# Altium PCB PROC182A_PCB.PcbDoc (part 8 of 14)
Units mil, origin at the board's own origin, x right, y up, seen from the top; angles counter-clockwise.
Board outline 3168.31 x 3700.79 mil, 8 copper layers (Top Layer, L2_GND1, L3_SIG1, L4_PWR1, L5_PWR2, L6_SIG2, L7_GND2, Bottom Layer), stack 58.1 mil thick; 580 components, 391 nets, 8314 pads, 4370 vias.
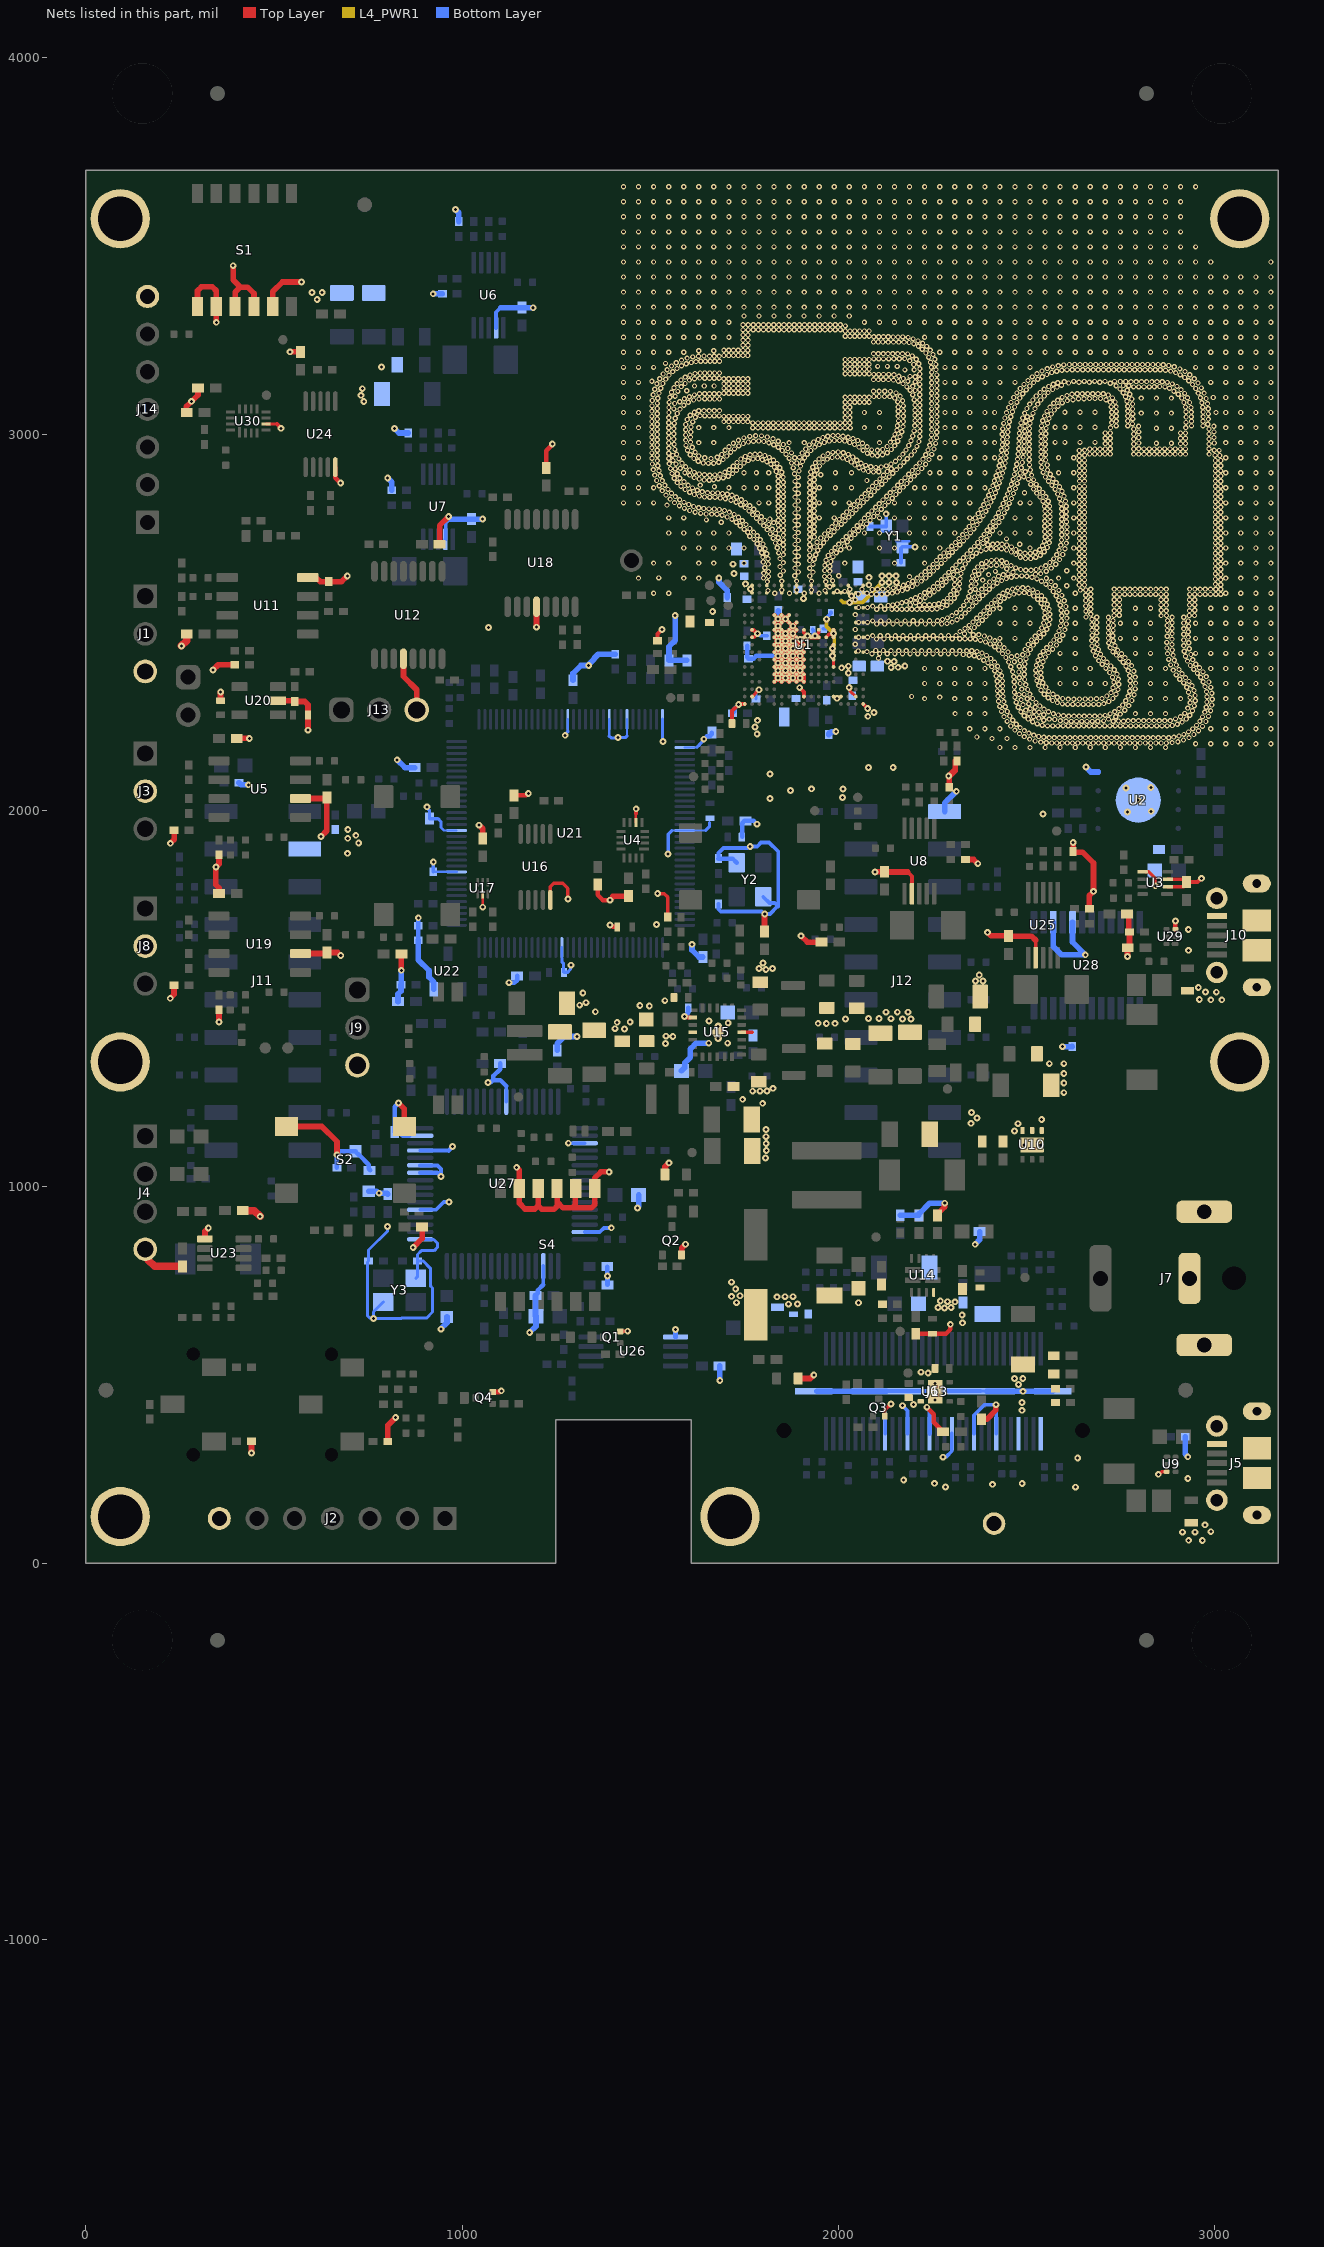
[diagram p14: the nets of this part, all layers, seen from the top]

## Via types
v1: diameter 13.77, hole 7, Top Layer to L2_GND1, tented both sides, 3444 vias
v2: diameter 18, hole 8, Top Layer to Bottom Layer, tented both sides, 911 vias
v3: diameter 13.77, hole 7, Top Layer to L2_GND1, tented top, 9 vias
v4: diameter 19.68, hole 7.87, Top Layer to Bottom Layer, 4 vias
v5: diameter 19.68, hole 7.87, Top Layer to Bottom Layer, tented both sides, 2 vias

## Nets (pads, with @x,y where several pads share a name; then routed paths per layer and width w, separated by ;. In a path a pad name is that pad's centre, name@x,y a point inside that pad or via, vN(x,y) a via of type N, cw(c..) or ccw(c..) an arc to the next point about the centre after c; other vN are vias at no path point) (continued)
GND: C1.1 C2.1 C3.1 C4.1 C5.1 C6.2 C7.1 C8.1 C9.1 C10.1 C11.1 C12.1 C13.2 C14.1 C15.2 C16.1 C17.1 C18.1 C19.1 C20.1 C21.1 C22.1 C24.1 C25.1 C26.1 C27.1 C30.2 C31.2 C32.1 C33.1 C34.2 C35.1 C36.2 C37.1 C38.1 C39.1 C40.2 C41.2 C42.1 C43.2 C44.2 C45.1 C46.1 C47.2 C48.2 C49.2 C50.2 C51.2 C52.1 C53.2 C54.2 C55.2 C56.2 C57.2 C58.2 C59.2 C60.2 C61.2 C62.2 C63.2 C64.2 C65.2 C66.2 C67.1 C68.2 C70.2 C71.2 C72.1 C73.2 C74.2 C75.1 C76.2 C77.1 C78.1 C79.2 C80.2 C81.2 C82.1 C83.2 C84.2 C85.1 C86.1 C87.2 C88.1 C89.2 C90.2 C91.1 C92.2 C93.2 C94.2 C95.1 C96.1 C97.1 C98.1 C99.1 C100.2 C102.1 C103.1 C104.2 C105.2 C106.1 C107.2 C108.2 C109.1 C110.1 C111.1 C112.1 C113.1 C114.2 C115.2 C116.1 C117.1 C118.1 C119.2 C120.2 C121.1 C123.2 C124.2 C125.1 C126.1 C127.2 C128.2 C130.2 C131.1 C132.2 C133.2 C134.1 C135.2 C136.2 C137.2 C138.2 C139.2 C140.2 C141.2 C142.1 C143.2 C144.2 C145.2 C146.1 C147.2 C148.2 C149.1 C150.2 C151.1 C152.2 C153.2 C154.1 C155.1 C156.1 C157.1 C158.2 D6.1 D10.1 J1.3 J2.7 J3.2 J4.4 J5.5 J5.6 J5.7 J5.8 J5.9 J5.10 J5.11 J6.18 J6.24 J6.30 J6.36 J6.42 J6.48 J6.54 J6.60 J6.MP1 J6.MP2 J6.MP3 J6.MP4 J7.2 J7.S1 J7.S2 J8.2 J9.3 J10.5 J10.6 J10.7 J10.8 J10.9 J10.10 J10.11 J11.4 J12.2 J13.3 J14.7 pad.TH1 pad.TH2 pad.TH9 Q1.2 Q2.2 Q3.2 Q4.2 R6.1 R10.2 R11.1 R20.1 R23.1 R33.1 R57.1 R71.1 R72.1 R73.2 R74.1 R75.1 R84.1 R86.1 R92.1 R101.1 R103.1 R113.1 R114.1 R116.1 R117.1 R144.1 R148.1 R150.1 R158.1 R162.1 R191.2 R194.2 R205.1 R208.1 R215.2 R218.1 R234.1 R239.1 R260.1 R265.2 R272.1 R276.2 R289.1 S1.7 S1.8 S1.9 S1.10 S1.11 S2.1 S2.2 S4.7 S4.8 S4.9 S4.10 S4.11 TP21.1 U1.A1 U1.A2 U1.A4 U1.A6 U1.A8 U1.A10 U1.A17 U1.B2 U1.B3 U1.B4 U1.B5 U1.B6 U1.B7 U1.B8 U1.B9 U1.B10 U1.B16 U1.C1 U1.C2 U1.D2 U1.D16 U1.E1 U1.E2 U1.E7 U1.E8 U1.E9 U1.E10 U1.E11 U1.E12 U1.E16 U1.F1 U1.F2 U1.F8 U1.G2 U1.G7 U1.G8 U1.H1 U1.H2 U1.H8 U1.J2 U1.J7 U1.J8 U1.J9 U1.J10 U1.J11 U1.J12 U1.J13 U1.J14 U1.J16 U1.K1 U1.K2 U1.K6 U1.K7 U1.K8 U1.K9 U1.K10 U1.K11 U1.K12 U1.K13 U1.K14 U1.L2 U1.L5 U1.L6 U1.L7 U1.L8 U1.L9 U1.L10 U1.L11 U1.L12 U1.L13 U1.L14 U1.M1 U1.M2 U1.M5 U1.M6 U1.M7 U1.M8 U1.M9 U1.M10 U1.M11 U1.M12 U1.M13 U1.M14 U1.N2 U1.N5 U1.N6 U1.N7 U1.N8 U1.N9 U1.N10 U1.N11 U1.N12 U1.N13 U1.N14 U1.P1 U1.P2 U1.T1 U1.T2 U1.T7 U1.T8 U1.T16 U1.U1 U1.U17 U2.4 U2.9 U3.2 U3.3 U3.5 U4.6 U5.2 U6.7 U7.7 U8.7 U9.3 U10.1 U10.2 U10.3 U10.7@2514.32,1111.65 U11.4 U12.4 U13.3 U13.7@2256.79,455.74 U14.12 U15. U15.2 U15.4 U15.16 U16.5 U17.2 U18.4 U19.2 U20.2 U21.10 U21.17 U21.48 U21.55 U21.58 U21.64 U21.66 U21.80 U21.114 U22.2 U23.5 U24.5 U25.7 U26.5 U27.1 U27.5 U27.10 U27.11 U27.13 U27.15 U27.25 U27.35 U27.47 U27.51 U28.3 U28.5 U29.3 U30.6 Y1.2 Y1.4 Y2.2 Y2.4 Y3.2 Y3.4 | length 15387.5
  Top Layer w6.5: v2(1054.79,1743.16) U17.2@1054.8,1778.05
  Top Layer w7: U30.6@479.11,3026.97 507.72,3026.97 ; U4.6@1461.61,1968.51 1461.61,1991.8
  Top Layer w8: U1.E9@1985.76,2441.69 U1.E9@1986.81,2440.64 1983.66,2437.48 v2(1983.66,2430.8) 1983.66,2424.11 U1.E10@1986.81,2420.95 1986.46,2420.6 1986.46,2416.62 1983.66,2413.82 v2(1983.66,2411.11) 1984.8,2411.11 1986.81,2409.1 U1.E11@1986.81,2401.27 U1.E12@1986.81,2381.58 ; v2(2028.18,2326.97) 2030.1,2325.05 2030.1,2318.62 2045.54,2303.17 U1.B16@2045.54,2302.84
  Top Layer w9: U16.5@1234.33,1762.65 1234.33,1798.01 1243.1,1806.78 1267.22,1806.78 1280.94,1793.06 v2(1280.94,1765.37) ; v2(1519.49,1779.4) 1537.53,1779.4 1546.55,1770.39 R57.1@1546.55,1717.55 ; U1.T16@1770.28,2302.84 v2@1788.4,2320.97 ; U1.J7@1908.07,2480.01 1908.07,2472.18 1916.09,2464.17 v2(1917.92,2464.17) ; v2(1937.6,2464.17) 1939.43,2464.17 1947.44,2472.18 U1.G7@1947.44,2480.01
  Top Layer w10: Q1.2@1419.8,616.56 1439.75,616.56 v2(1439.97,616.79) ; C134.1@1519.16,2451.53 1519.16,2468.93 v2(1531.31,2481.08) ; C17.1@1717.02,2231.45 1717.02,2264.29 v2(1734.8,2282.07) ; v2@1734.22,2282.76 1734.61,2283.16 U1.U17@1750.59,2283.16 ; U15.16@1742.75,1410.77 1769.85,1410.77 ; U1.T8@1770.28,2460.32 1775.03,2460.32 v2(1784.53,2469.83) 1774.35,2480.01 U1.T7@1770.28,2480.01 ; v2(1896.78,2326.45) 1908.07,2315.15 U1.J16@1908.07,2302.84 ; U1.F8@1967.13,2460.32 1975.47,2468.67 1985.47,2468.67 v2(1986.97,2470.17) 1986.97,2460.48 U1.E8@1986.81,2460.32 ; v2@1986.81,2470.17 U1.E7@1986.81,2480.01 ; U1.A17@2065.55,2283.16 2077.55,2271.16 v2(2077.55,2270.86) ; C59.2@2121.92,1837.35 C59.2@2122.64,1836.64 ; Q3.2@2122.86,391.35 2122.86,407.24 v2(2139.13,423.5) ; 2183.9,1836.64 2194.92,1825.61 U8.7@2194.92,1779.27 ; C133.2@2450.77,1667.11 C133.2@2451.49,1666.39 ; U25.7@2523.77,1609.02 2523.77,1655.37 ; U3.5@2816.74,1837.23 2824.24,1837.23 2841.54,1819.94 v2(2841.54,1800.2) ; v2(2849.59,236.71) 2851.76,236.71 2858.58,243.53 U9.3@2871.71,243.53 ; U3.2@2874.89,1797.86 2916.51,1797.86 2924.66,1806.01 C36.2@2924.66,1809.95 ; U3.3@2874.89,1817.54 2917.06,1817.54 C36.2@2924.66,1809.95 ; v2(2963.98,1819.91) 2954.01,1809.95 C36.2@2924.66,1809.95
  Top Layer w10.8: 507.72,3026.97 518.82,3015.86 v2(518.82,3015.49) ; 1461.61,1991.8 1461.61,2004.04 v2(1462.35,2004.78) ; v2(1590.68,1452.8) 1592.05,1451.42 1597.18,1451.42 1598.46,1450.14 U15.2@1606.42,1450.14 ; U1.T16@1770.95,2302.84 U1.T16@1770.95,2303.01 ; U1.N14@1829.33,2342.21 v2(1839.18,2352.06) ; U1.N5@1829.33,2519.38 v2(1839.18,2509.54) ; U1.L5@1868.7,2519.38 v2(1858.86,2509.54) ; U1.K6@1888.39,2499.69 v2(1878.55,2489.85) ; v2@1917.76,2460.32 U1.J8@1908.07,2460.32 v2@1898.23,2450.48 ; v2@1918.07,2460.32 U1.H8@1927.76,2460.32 v2@1937.44,2460.32 ; v2@1937.76,2460.32 U1.G8@1947.44,2460.32 ; v2(1839.18,2352.06) U1.M13@1849.02,2361.9 ; v2(1839.18,2352.06) U1.N13@1829.33,2361.9 v2(1839.18,2371.74) ; v2(1839.18,2352.06) U1.M14@1849.02,2342.21 v2(1858.86,2352.06) ; v2(1839.18,2371.74) U1.M12@1849.02,2381.58 ; v2(1839.18,2371.74) U1.M13@1849.02,2361.9 ; v2(1839.18,2371.74) U1.N12@1829.33,2381.58 v2(1839.18,2391.43) ; v2(1839.18,2391.43) U1.M11@1849.02,2401.27 ; v2(1839.18,2391.43) U1.M12@1849.02,2381.58 ; v2(1839.18,2391.43) U1.N11@1829.33,2401.27 v2(1839.18,2411.11) ; v2(1839.18,2411.11) U1.M10@1849.02,2420.95 ; v2(1839.18,2411.11) U1.M11@1849.02,2401.27 ; v2(1839.18,2411.11) U1.N10@1829.33,2420.95 v2(1839.18,2430.8) ; v2(1839.18,2430.8) U1.M9@1849.02,2440.64 ; v2(1839.18,2430.8) U1.M10@1849.02,2420.95 ; v2(1839.18,2430.8) U1.N9@1829.33,2440.64 v2(1839.18,2450.48) ; v2(1839.18,2450.48) U1.M8@1849.02,2460.32 ; v2(1839.18,2450.48) U1.M9@1849.02,2440.64 ; v2(1839.18,2450.48) U1.N8@1829.33,2460.32 v2(1839.18,2470.17) ; v2(1839.18,2470.17) U1.M7@1849.02,2480.01 ; v2(1839.18,2470.17) U1.N7@1829.33,2480.01 v2(1839.18,2489.85) ; v2(1839.18,2470.17) U1.M8@1849.02,2460.32 ; v2(1839.18,2489.85) U1.M6@1849.02,2499.69 ; v2(1839.18,2489.85) U1.M7@1849.02,2480.01 ; v2(1839.18,2489.85) U1.N6@1829.33,2499.69 v2(1839.18,2509.54) ; v2(1839.18,2509.54) U1.M6@1849.02,2499.69 ; v2(1839.18,2509.54) U1.M5@1849.02,2519.38 v2(1858.86,2509.54) ; U1.M13@1849.02,2361.9 v2(1858.86,2371.74) ; U1.M13@1849.02,2361.9 v2(1858.86,2352.06) ; U1.M12@1849.02,2381.58 v2(1858.86,2391.43) ; U1.M12@1849.02,2381.58 v2(1858.86,2371.74) ; U1.M11@1849.02,2401.27 v2(1858.86,2411.11) ; U1.M11@1849.02,2401.27 v2(1858.86,2391.43) ; U1.M10@1849.02,2420.95 v2(1858.86,2430.8) ; U1.M10@1849.02,2420.95 v2(1858.86,2411.11) ; U1.M9@1849.02,2440.64 v2(1858.86,2450.48) ; U1.M9@1849.02,2440.64 v2(1858.86,2430.8) ; U1.M8@1849.02,2460.32 v2(1858.86,2470.17) ; U1.M8@1849.02,2460.32 v2(1858.86,2450.48) ; U1.M7@1849.02,2480.01 v2(1858.86,2470.17) ; U1.M6@1849.02,2499.69 v2(1858.86,2509.54) ; v2(1858.86,2352.06) U1.L14@1868.7,2342.21 v2(1878.55,2352.06) ; v2(1858.86,2352.06) U1.L13@1868.7,2361.9 ; v2(1858.86,2371.74) U1.L13@1868.7,2361.9 ; v2(1858.86,2371.74) U1.L12@1868.7,2381.58 ; v2(1858.86,2391.43) U1.L12@1868.7,2381.58 ; v2(1858.86,2391.43) U1.L11@1868.7,2401.27 ; v2(1858.86,2411.11) U1.L11@1868.7,2401.27 ; v2(1858.86,2411.11) U1.L10@1868.7,2420.95 ; v2(1858.86,2430.8) U1.L9@1868.7,2440.64 ; v2(1858.86,2430.8) U1.L10@1868.7,2420.95 ; v2(1858.86,2450.48) U1.L8@1868.7,2460.32 ; v2(1858.86,2450.48) U1.L9@1868.7,2440.64 ; v2(1858.86,2470.17) U1.L7@1868.7,2480.01 ; v2(1858.86,2470.17) U1.L8@1868.7,2460.32 ; v2(1858.86,2509.54) U1.L6@1868.7,2499.69 v2(1878.55,2489.85) ; U1.L13@1868.7,2361.9 v2(1878.55,2371.74) ; U1.L13@1868.7,2361.9 v2(1878.55,2352.06) ; U1.L12@1868.7,2381.58 v2(1878.55,2391.43) ; U1.L12@1868.7,2381.58 v2(1878.55,2371.74) ; U1.L11@1868.7,2401.27 v2(1878.55,2411.11) ; U1.L11@1868.7,2401.27 v2(1878.55,2391.43) ; U1.L10@1868.7,2420.95 v2(1878.55,2430.8) ; U1.L10@1868.7,2420.95 v2(1878.55,2411.11) ; U1.L9@1868.7,2440.64 v2(1878.55,2450.48) ; U1.L9@1868.7,2440.64 v2(1878.55,2430.8) ; U1.L8@1868.7,2460.32 v2(1878.55,2470.17) ; U1.L8@1868.7,2460.32 v2(1878.55,2450.48) ; U1.L7@1868.7,2480.01 v2(1878.55,2489.85) ; U1.L7@1868.7,2480.01 v2(1878.55,2470.17) ; v2(1878.55,2352.06) U1.K14@1888.39,2342.21 v2(1898.23,2352.06) ; v2(1878.55,2352.06) U1.K13@1888.39,2361.9 ; v2(1878.55,2371.74) U1.K13@1888.39,2361.9 ; v2(1878.55,2371.74) U1.K12@1888.39,2381.58 ; v2(1878.55,2391.43) U1.K12@1888.39,2381.58 ; v2(1878.55,2391.43) U1.K11@1888.39,2401.27 ; v2(1878.55,2411.11) U1.K10@1888.39,2420.95 ; v2(1878.55,2411.11) U1.K11@1888.39,2401.27 ; v2(1878.55,2430.8) U1.K9@1888.39,2440.64 ; v2(1878.55,2430.8) U1.K10@1888.39,2420.95 ; v2(1878.55,2450.48) U1.K8@1888.39,2460.32 ; v2(1878.55,2450.48) U1.K9@1888.39,2440.64 ; v2(1878.55,2470.17) U1.K7@1888.39,2480.01 v2(1878.55,2489.85) ; v2(1878.55,2470.17) U1.K8@1888.39,2460.32 ; U1.K13@1888.39,2361.9 v2(1898.23,2371.74) ; U1.K13@1888.39,2361.9 v2(1898.23,2352.06) ; U1.K12@1888.39,2381.58 v2(1898.23,2391.43) ; U1.K12@1888.39,2381.58 v2(1898.23,2371.74) ; U1.K11@1888.39,2401.27 v2(1898.23,2411.11) ; U1.K11@1888.39,2401.27 v2(1898.23,2391.43) ; U1.K10@1888.39,2420.95 v2(1898.23,2430.8) ; U1.K10@1888.39,2420.95 v2(1898.23,2411.11) ; U1.K9@1888.39,2440.64 v2@1898.23,2450.48 ; U1.K9@1888.39,2440.64 v2(1898.23,2430.8) ; U1.K8@1888.39,2460.32 v2@1898.23,2450.48 ; v2(1898.23,2352.06) U1.J14@1908.07,2342.21 U1.J13@1908.07,2361.9 ; v2(1898.23,2352.06) U1.J13@1908.07,2361.9 ; v2(1898.23,2371.74) U1.J12@1908.07,2381.58 v2(1898.23,2391.43) ; v2(1898.23,2371.74) U1.J13@1908.07,2361.9 ; v2(1898.23,2391.43) U1.J11@1908.07,2401.27 v2(1898.23,2411.11) ; v2(1898.23,2411.11) U1.J10@1908.07,2420.95 v2(1898.23,2430.8) ; v2(1898.23,2430.8) U1.J9@1908.07,2440.64 v2@1898.23,2450.48
  Top Layer w12: U24.5@663.06,2912.26 663.06,2883.9 v2@676.55,2870.41 ; Q4.2@1081.12,455.3 1099.39,455.3 1102.49,458.4 v2(1104.11,458.4) ; C104.2@1138.39,2040.95 1169.79,2040.95 1174.26,2045.42 v2(1175.88,2045.42) ; C107.2@1223.43,2910.43 1223.43,2956.07 1239.47,2972.12 v2(1239.47,2973.64) ; R6.1@1360.12,1803.04 1360.12,1775.81 1374.18,1761.75 v2(1392.87,1761.75) ; v2(1392.85,1696.19) 1394.47,1696.19 1399.74,1690.92 C108.2@1411.68,1690.92 ; R33.1@2205.06,610.03 C68.2@2250.06,610.03 2285.5,610.03 2296.93,621.46 v2(2296.93,635.19) ; v2(2234.52,414.95) 2252.92,396.55 2252.92,374.8 R92.1@2277.93,349.8 ; U29.3@2895.04,1684.93 2895.14,1685.03 2895.14,1706.42 v2(2895.24,1706.52)
  Top Layer w15: v2@224.29,1501.17 234.64,1511.53 C111.1@234.64,1535.77 ; v2@224.45,1912.88 234.81,1923.24 C39.1@234.81,1947.48 ; C136.2@267.48,3058.04 267.48,3073.34 v2(281.32,3087.18) 298.33,3104.19 R272.1@298.33,3122.76 ; S1.7@296.89,3339.18 296.89,3380.93 307.23,3391.28 336.46,3391.28 346.89,3380.85 S1.8@346.89,3339.18 347.04,3339.03 347.04,3298.64 346.23,3297.83 v2@345.5,3297.83 ; U23.5@316.77,861.92 316.77,882.42 v2(325.68,891.33) ; v2(338.4,2373.72) 351.92,2387.24 R158.1@395.99,2387.24 ; R144.1@354.01,1470.77 v2(354.07,1438.37) v2(354.07,1438.37) ; C109.1@354.01,1780.14 354.01,1794.45 345.82,1802.65 v2(345.82,1849.79) 354.18,1858.16 R71.1@354.18,1882.48 ; v2(391.82,3447.44) 391.82,3409.39 410.58,3390.63 ; S1.9@396.89,3339.18 396.89,3376.94 410.58,3390.63 ; C38.1@401.43,2191.85 434.53,2191.85 v2(434.67,2191.71) ; R205.1@440.06,324.05 440.26,323.84 440.26,293.56 v2(440.46,293.36) ; S1.10@446.89,3339.18 446.89,3373.53 429.78,3390.63 410.58,3390.63 ; S1.11@496.89,3339.18 496.89,3378.58 522.58,3404.27 v2(573.04,3404.27) ; U20.2@510.67,2291.81 553.7,2291.81 R86.1@555.67,2289.84 581.89,2289.84 590.67,2281.05 C51.2@590.67,2254.41 590.67,2213.66 v2(590.45,2213.43) ; S2.1@533.56,1160.78 627.16,1160.78 667.43,1120.51 v2(667.43,1085.32) ; v2(542.61,3218.78) 542.87,3218.52 570.41,3218.52 C135.2@570.67,3218.25 ; U19.2@570.55,1620.14 637.79,1620.14 C110.1@640.55,1622.9 669.23,1622.9 677.18,1614.95 v2(677.54,1614.95) ; U5.2@570.72,2031.85 637.96,2031.85 C37.1@640.38,2034.28 ; U11.4@590.18,2618.79 612.27,2618.79 622.9,2608.16 R162.1@645.19,2608.16 679.63,2608.16 v2(694.92,2623.45) ; v2(624.89,1930.93) 640.38,1946.42 C37.1@640.38,2034.28 ; C37.1@640.72,2034.61 C37.1@640.38,2034.28 ; R208.1@802.51,323.68 802.51,366.63 v2(823.56,387.69) ; v2(830.97,1223.09) 846.55,1207.51 S2.2@846.55,1160.78 ; v2(838.3,1575.48) 838.54,1575.71 838.54,1618.61 R215.2@838.78,1618.85 ; U12.4@844.1,2403.24 844.1,2356.36 879.43,2321.03 J13.3@879.43,2267.59 ; v2(870.14,838.96) 893.8,862.62 C53.2@893.8,893.61 ; C41.2@940.24,2707.58 940.24,2757.15 v2(964.38,2781.29) ; v2(1045.06,1961.26) 1054.8,1951.51 C52.1@1054.8,1925.79 ; v2(1145.08,1052.14) 1152.05,1045.17 S4.11@1152.05,996.11 1152.05,956.62 1167.13,941.54 1193.23,941.54 1202.02,950.33 ; v2(1197.46,2487.03) 1197.57,2487.14 1197.57,2541.45 U18.4@1197.68,2541.56 ; S4.10@1202.05,996.11 1202.02,950.33 ; S4.9@1252.05,996.11 1252.56,995.6 1252.56,960.28 ; S4.8@1302.05,996.11 1300.91,994.97 1300.91,953.23 1292.12,944.44 ; S4.7@1352.05,996.11 1352.05,1023.61 1368.61,1040.18 1389.16,1040.18 1389.34,1040 1389.8,1040 v2@1389.97,1040.18 ; S4.7@1352.55,995.61 1352.55,953.23 1343.76,944.44 1292.12,944.44 ; v2(1392.87,1761.75) 1392.87,1762.56 1400.48,1770.17 1400.48,1772.77 C40.2@1441.72,1772.77 ; D10.1@1538.71,1033.48 1538.82,1033.59 1538.82,1053.55 v2(1549.43,1064.16) ; Q2.2@1583.09,819.67 1583.09,837.18 v2(1593.74,847.83) ; D6.1@1892.72,491.14 1924.72,491.14 v2(1934.22,500.65) ; v2(1900.43,1667.13) 1917.08,1650.47 R265.2@1954.86,1650.47 ; v2(2097.03,1836.9) 2097.26,1837.13 2121.7,1837.13 C59.2@2121.92,1837.35 ; C59.2@2122.64,1836.64 2183.9,1836.64 ; R74.1@2263.39,924.54 2263.39,928.48 2281.63,946.72 2281.63,956.31 v2(2282.21,956.89) ; v2@2292.68,2090.9 v2@2293.55,2090.03 ; v2(2292.68,2091.72) 2309.66,2108.69 ; R117.1@2293.97,2061.87 v2@2293.97,2088.58 ; v2@2294.26,2090.13 2309.66,2105.53 2309.66,2108.69 ; R276.2@2309.66,2131.89 2309.66,2108.69 ; R116.1@2337.61,1869.92 2359.03,1869.92 v2(2370.04,1858.92) ; R11.1@2379.68,382.91 2393.99,382.91 2418.12,407.04 v2(2418.12,421.59) ; v2(2396.05,1676.58) 2405.52,1667.11 C133.2@2450.77,1667.11 ; C133.2@2451.49,1666.39 2512.75,1666.39 2523.77,1655.37 ; R150.1@2622.83,1891.62 2622.83,1889.65 R150.1@2623.14,1889.65 ; R150.1@2623.14,1889.34 R150.1@2623.14,1889.65 ; v2(2623.45,1915.14) 2623.14,1914.83 R150.1@2623.14,1889.65 ; R148.1@2666.46,1739.68 2666.46,1774.32 v2@2677.25,1785.11 ; v2(2677.25,1785.49) 2677.25,1860.56 2648.16,1889.65 R150.1@2623.14,1889.65 ; C56.2@2766.69,1725.45 2770.89,1721.25 2770.89,1679.64 R260.1@2773.11,1677.42 2773.11,1639.72 2767.87,1634.49 2767.87,1612.54 v2(2767.45,1612.12) ; 1202.02,950.33 1211.83,940.52 1243.77,940.52 1252.56,949.3 1252.56,960.28 ; 1252.56,960.28 1268.4,944.44 1292.12,944.44
  Top Layer w16: C112.1@358.31,2291.81 358.31,2315.18 v2(358.45,2315.32) ; R84.1@1803.41,1679.25 1803.59,1679.43 1803.59,1725.05 v2(1803.97,1725.44)
  Top Layer w20: J4.4@158.07,834.5 166.29,826.28 166.29,805.83 183.05,789.08 C132.2@256.77,789.08 ; v2(254.13,2437.45) 268.37,2451.69 C65.2@268.37,2468.79 ; C123.2@417.15,937.13 448.3,937.13 v2(463.4,922.04)
  L4_PWR1 w10: v2(1967.95,2508.48) 1967.95,2489.19 v2(1986.97,2470.17) 1988.5,2468.64 1988.5,2437.8 1983.66,2432.96 v2(1983.66,2430.8) ; 2008.2,2557.33 2012.45,2553.09 v2(2029.78,2553.09) 2063.29,2553.09 v2(2115.84,2605.63)
  Bottom Layer w6: 943.92,1955.22 951.89,1947.26 U21.17@985.36,1947.26 ; 1280.53,2210.56 U21.48@1280.53,2242.37 ; 1390.87,2197.77 U21.55@1390.87,2242.47 ; 1438.11,2198.9 U21.58@1438.11,2242.47 ; 1557.47,1946.79 1557.88,1947.19 U21.80@1591.66,1947.19 1646.93,1947.19 ; U21.66@1591.66,2167.67 1623.73,2167.67 ; 2108.55,2741.08 2142.77,2741.08 ; 2153.44,2715.68 2187.65,2715.68
  Bottom Layer w7: C115.2@923.91,1836.96 U21.10@985.36,1836.96 ; U21.114@1264.89,1636.17 1264.95,1612.25 1265.05,1612.14 1265.05,1608.47 1265.2,1608.33 1265.2,1598.11 1266.05,1597.26
  Bottom Layer w8: Y3.2@790.5,694.34 764.51,668.35 v2(764.51,650.57) ; v2(802.08,894.99) 802.08,883.22 751.38,832.52 C147.2@751.38,803.24 748.58,800.44 748.58,657.71 753.81,652.49 762.6,652.49 v2(764.51,650.57) ; Y3.4@877.11,757.33 881.26,761.48 C148.2@881.26,803.24 ; U27.1@888.88,860.66 924.41,860.66 934.13,850.94 934.13,839.14 925.69,830.7 891.66,830.7 881.26,820.29 C148.2@881.26,803.24 ; J6.MP3@2376.82,457.65 2393.47,457.65 J6.MP3@2393.7,457.42 ; v2(764.51,650.57) 764.96,651.02 838.86,651.02 839.31,651.47 905.17,651.47 921.24,667.54 921.24,731.75 915.67,737.32 915.67,784.4 896.83,803.24 C148.2@881.26,803.24
  Bottom Layer w8.7: v2(906.6,2010.04) 906.6,2007.52 913.07,2001.05 C116.1@913.07,1978.49 936.06,1978.49 943.92,1970.63 943.92,1955.22 ; C115.2@923.42,1837.44 923.49,1837.51 923.49,1863.23 v2(923.55,1863.29) ; 1266.05,1597.26 1269.09,1594.22 1269.09,1572.03 C127.2@1270.8,1570.32 ; C127.2@1271.13,1570.65 1280.8,1570.65 1287.87,1577.71 1287.87,1587.55 v2(1289.54,1589.21) ; v2(1273.89,2199.95) 1273.89,2202.46 1280.53,2209.1 1280.53,2210.56 ; v2(1281.96,1116.34) 1282.07,1116.45 1325.77,1116.45 U27.35@1325.89,1116.56 ; 1390.87,2197.77 1395.57,2193.07 1413.3,2193.07 v2(1414.23,2194) ; v2@1414.23,2193.4 1414.83,2194 1433.22,2194 1438.11,2198.9 ; U21.64@1532.6,2242.47 1532.6,2184.6 v2(1533.54,2183.66) ; v2(1547.1,1884.39) 1547.29,1884.58 1547.29,1936.92 1557.16,1946.79 1557.47,1946.79 ; 1623.73,2167.67 1629.88,2173.82 1629.88,2174.98 1642.03,2187.14 v2(1642.03,2189.6) ; 1646.93,1947.19 1657,1957.26 1657,1968.25 ; C1.1@1780.57,2296.34 1780.57,2312.47 v2(1789.07,2320.97)
  Bottom Layer w10: U27.5@888.88,939.4 930.81,939.4 951.27,959.85 v2(965.32,959.85) ; U27.13@888.88,1096.88 964.04,1096.88 ; U7.7@955.74,2720.53 956.52,2721.31 956.52,2767.65 957.8,2768.93 ; U6.7@1090.15,3282.32 1090.15,3323.71 1102.6,3336.16 ; U27.25@1117.22,1226.8 1117.22,1268.23 ; 1215.65,740.25 U27.51@1215.65,789.79 ; U27.47@1325.89,880.34 1365.81,880.34 1376.6,891.13 1396.1,891.13 v2(1396.43,891.46) ; C97.1@1681.09,1751.94 1681.09,1737.63 1686.94,1731.77 1795.48,1731.77 1801.81,1725.44 v2(1803.97,1725.44) 1817.93,1725.44 1838.56,1746.06 ; C98.1@1681.09,1872.51 1681.09,1887.27 1694.28,1900.46 1758.68,1900.46 1763.08,1904.86 v2(1765.25,1904.86) 1783.92,1904.86 1794.25,1915.2 1815.68,1915.2 1839.95,1890.93 1839.95,1744.67 1838.56,1746.06 ; C8.1@1718.82,2258.07 1718.99,2258.07 1723.83,2262.92 1723.83,2271.11 v2(1734.8,2282.07) ; v2@1785.01,2469.35 1787.17,2469.35 1792.2,2464.32 C25.1@1809.62,2464.32 ; Y2.2@1800.24,1770.73 1816.89,1754.07 1830.55,1754.07 1838.56,1746.06 ; C22.1@1931.44,2481.01 1933.26,2479.19 1933.26,2468.67 1937.6,2464.33 v2(1937.6,2464.17) v2@1937.6,2462.17 ; C130.2@1959.17,2482.99 1974.14,2482.99 v2(1986.97,2470.17) ; v2(1967.95,2508.48) 1969.48,2510.01 1969.48,2513.56 1980.26,2524.33 C18.1@1980.26,2526.3 ; C32.1@2083.65,2754.96 2125.9,2754.96 Y1.2@2126.74,2755.8 v2(2126.74,2788.36) ; J6.18@2123.87,344.85 2123.87,408.24 v2(2139.13,423.5) ; J6.MP2@2126.82,457.65 J6.MP3@2376.82,457.65 ; C33.1@2165.66,2658.54 2165.66,2696.3 Y1.4@2170.04,2700.68 2202.61,2700.68 v2(2203.31,2699.98) ; v2(2169.68,418.91) 2182.92,405.67 J6.24@2182.92,344.85 ; v2(2277.39,282.01) 2278.92,283.55 2286.91,283.55 2301.03,297.67 J6.36@2301.03,344.85 ; J6.42@2360.09,344.85 2360.09,393.73 2387.95,421.59 v2(2418.12,421.59) 2419.14,420.56 J6.48@2419.14,344.85
  Bottom Layer w11: U27.10@888.88,1037.82 934.06,1037.82 v2(944.06,1027.82) 944.06,1047.87 934.42,1057.51 U27.11@888.88,1057.51
  Bottom Layer w12: R218.1@667.22,1050.68 667.22,1085.11 v2(667.43,1085.32) 677.64,1095.53 C145.2@717.97,1095.53 ; C145.2@716.55,1094.58 716.55,1093.59 726.3,1083.84 727.28,1083.84 751.68,1059.44 751.68,1047.98 C146.1@755.59,1044.07 ; v2(830.97,1223.09) 821.09,1213.21 C140.2@821.09,1145.61 832.48,1145.61 841.84,1136.25 U27.15@859.45,1136.25 ; R239.1@883.49,1655.53 C118.1@883.49,1693.47 ; C118.1@883.52,1693.5 883.52,1714.95 v2(883.61,1715.04) ; 964.04,1096.88 v2@974.5,1107.33 ; v2(1068.76,1277.35) 1069.91,1278.5 1076.37,1278.5 1083.14,1285.27 1083.29,1285.27 ; C153.2@1101.06,1328.2 1101.06,1313 1083.29,1295.23 1083.29,1285.27 ; 1117.22,1268.23 1117.07,1268.23 1101.18,1284.13 1082.14,1284.13 1083.29,1285.27 ; v2(1124.87,1542.6) 1139.11,1542.6 1146.14,1549.63 C126.1@1146.14,1560.6 ; C150.2@1195.07,711.79 1195.69,711.79 1201.51,717.6 1201.51,726.1 1215.62,740.22 ; C143.2@1385.71,788.5 1385.71,764.05 v2(1386.21,763.56) 1386.21,740.4 C144.2@1385.87,740.07 ; v2(1590.68,1452.8) 1600.32,1462.44 C79.2@1600.32,1475.87 ; v2(1642.03,2189.6) 1642.71,2189.6 1650.5,2197.39 1657.75,2197.39 1663.56,2203.2 C95.1@1663.56,2207.14 ; C98.1@1681.09,1872.51 1718.5,1872.51 Y2.4@1729.37,1861.63 ; C124.2@1743.98,1929.95 1743.98,1966.6 1749.79,1972.41 C125.1@1752.87,1972.41 1774.52,1972.41 v2(1783.2,1963.72) ; C7.1@1756.9,2437.91 1756.9,2407.43 C26.1@1760.53,2403.81 1774.58,2403.81 1781.82,2411.05 v2@1839.11,2411.05 ; v2(2234.52,414.95) 2234.52,413.6 2241.98,406.15 J6.30@2241.98,344.85
  Bottom Layer w13: U26.5@1566.92,601.51 1567.02,601.61 v2(1567.02,621.48)
  Bottom Layer w15: C119.2@407,2074.14 413,2068.14 431.86,2068.14 v2(432.07,2068.34) ; C141.2@752.28,988.78 772.21,988.78 777.43,983.56 v2(779.6,983.56) 799.63,983.56 C142.1@802.28,980.91 ; v2(802.28,2883.47) 813.05,2872.7 R113.1@813.06,2851.18 ; v2(820.62,3014.87) 832.36,3003.13 R114.1@856.69,3003.13 ; v2(827.43,2134.84) 848.09,2114.19 C106.1@874.28,2114.19 ; C99.1@829.75,1492.45 829.75,1512.5 837.62,1520.38 C102.1@837.62,1537.45 837.96,1537.79 837.96,1575.13 v2(838.3,1575.48) ; R239.1@883.49,1655.53 883.49,1603.31 911.89,1574.91 911.89,1557.59 924.77,1544.71 U22.2@924.77,1525.29 ; v2(923.18,3372.8) 923.26,3372.89 947.38,3372.89 R101.1@947.46,3372.97 ; v2(943.68,622.08) 944.25,622.65 944.25,623.91 959.67,639.33 C139.2@959.67,654.86 ; 957.8,2768.93 957.8,2773.9 964.38,2780.48 v2(964.38,2781.29) ; v2@963.24,2774.37 964.38,2774.37 1024.89,2774.37 C58.2@1025.06,2774.2 1025.21,2774.35 1054.35,2774.35 v2(1054.5,2774.5) ; v2(982.2,3596.92) 991.09,3588.03 R103.1@991.09,3564.92 ; 1102.6,3336.16 C57.2@1159.29,3336.16 1159.46,3335.99 1188.73,3335.99 v2(1188.9,3335.82) ; v2(1179.44,613.17) 1196.43,630.15 C149.1@1196.43,656.45 1195.07,657.81 C150.2@1195.07,711.79 ; C152.2@1252.76,1362.8 1252.76,1381.05 1271.49,1399.78 v2(1305.4,1399.78) ; C113.1@1294.66,2346.16 1294.66,2364.4 1315.52,2385.26 v2(1336.22,2385.26) ; v2@1335.19,2386.68 1351.1,2402.59 1351.1,2404.71 1361.7,2415.32 R234.1@1406.98,2415.32 ; v2(1465.58,943.91) 1465.58,944.72 1468.88,948.02 C151.1@1468.88,978.77 ; v2(1566.13,2518.38) 1566.13,2452.07 1549.54,2435.48 R194.2@1549.54,2398.92 R191.2@1596.96,2398.92 ; C88.1@1582.92,1308.62 1591.44,1317.13 1591.44,1329.82 1606.37,1344.75 1606.37,1366.69 1621.75,1382.07 v2(1655.21,1382.07) ; v2(1610.83,1644.78) 1610.83,1629.2 1629,1611.03 C94.2@1639.64,1611.03 ; v2(1681.86,2617.83) 1682.43,2617.26 1682.43,2606.61 1703.94,2585.1 C45.1@1703.94,2565.89 ; C138.2@1684.16,524.74 1684.39,524.51 1684.39,486.36 v2(1684.62,486.13) ; v2(1839.18,2509.54) 1839.55,2509.91 C6.2@1839.55,2531.16 ; J6.MP1@1942.77,457.65 J6.MP2@2126.82,457.65 ; C10.1@1973.8,2201.78 1973.8,2203.75 1976.14,2206.1 1978.11,2206.1 1981.18,2209.17 1992.06,2209.17 v2(1992.64,2209.74) ; R23.1@2163.93,924.94 2213.05,924.94 R20.1@2213.57,924.42 2213.57,928.36 2242.1,956.89 v2(2282.21,956.89) ; J12.2@2282,1997.45 2282,2020.19 v2(2312.82,2051.01) ; v2(2362.93,847.59) 2374.93,859.59 R75.1@2374.93,881.32 ; J6.MP3@2393.7,457.42 2490.07,457.42 v2(2490.3,457.19) ; v2@2490.3,457.65 J6.MP4@2569.34,457.65 ; U28.3@2570.36,1703.39 2570.36,1639.27 2592.96,1616.67 v2(2655.5,1616.67) 2621.55,1650.63 U28.5@2621.55,1703.39 ; v2(2595.11,1372.6) 2595.43,1372.92 2620.64,1372.92 R10.2@2620.96,1373.24 ; v2(2657.2,2115.39) 2670.01,2102.59 U2.4@2689.93,2102.59 ; R72.1@2921,336.63 2921,290.76 2927.8,283.96 v2(2927.8,283.15)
